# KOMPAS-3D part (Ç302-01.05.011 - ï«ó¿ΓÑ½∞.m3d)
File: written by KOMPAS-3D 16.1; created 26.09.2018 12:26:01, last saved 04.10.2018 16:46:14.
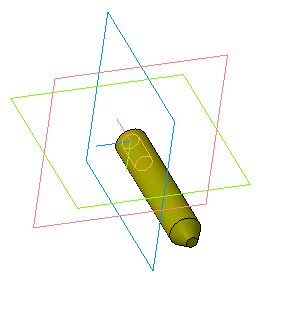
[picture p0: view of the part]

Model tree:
1. Эскиз:1
2. Операция вращения:1
     Угол 1 = 360
3. Отверстие:1
     Глубина выреза = 12; Диаметр отверстия = 4.13397; Угол конуса торца = 118
4. M5
     Длина резьбы = 10; Шаг резьбы = 0.8; Номинальный диаметр резьбы = 5
5. Фаска:1
     Угол = 45; Длина 1 = 1; Длина 2 = 1
6. Фаска:2  (labels: Сталь 40  ГОСТ 1050-2013; А302-01.05.011)
     Угол = 45; Длина 1 = 0.5; Длина 2 = 0.5

Referenced files in C:\Program Files\ASCON\KOMPAS-3D V16\Sys\Thread\: cil0_8724-2002 coarse.xml
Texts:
  Линейный размер с обрывом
